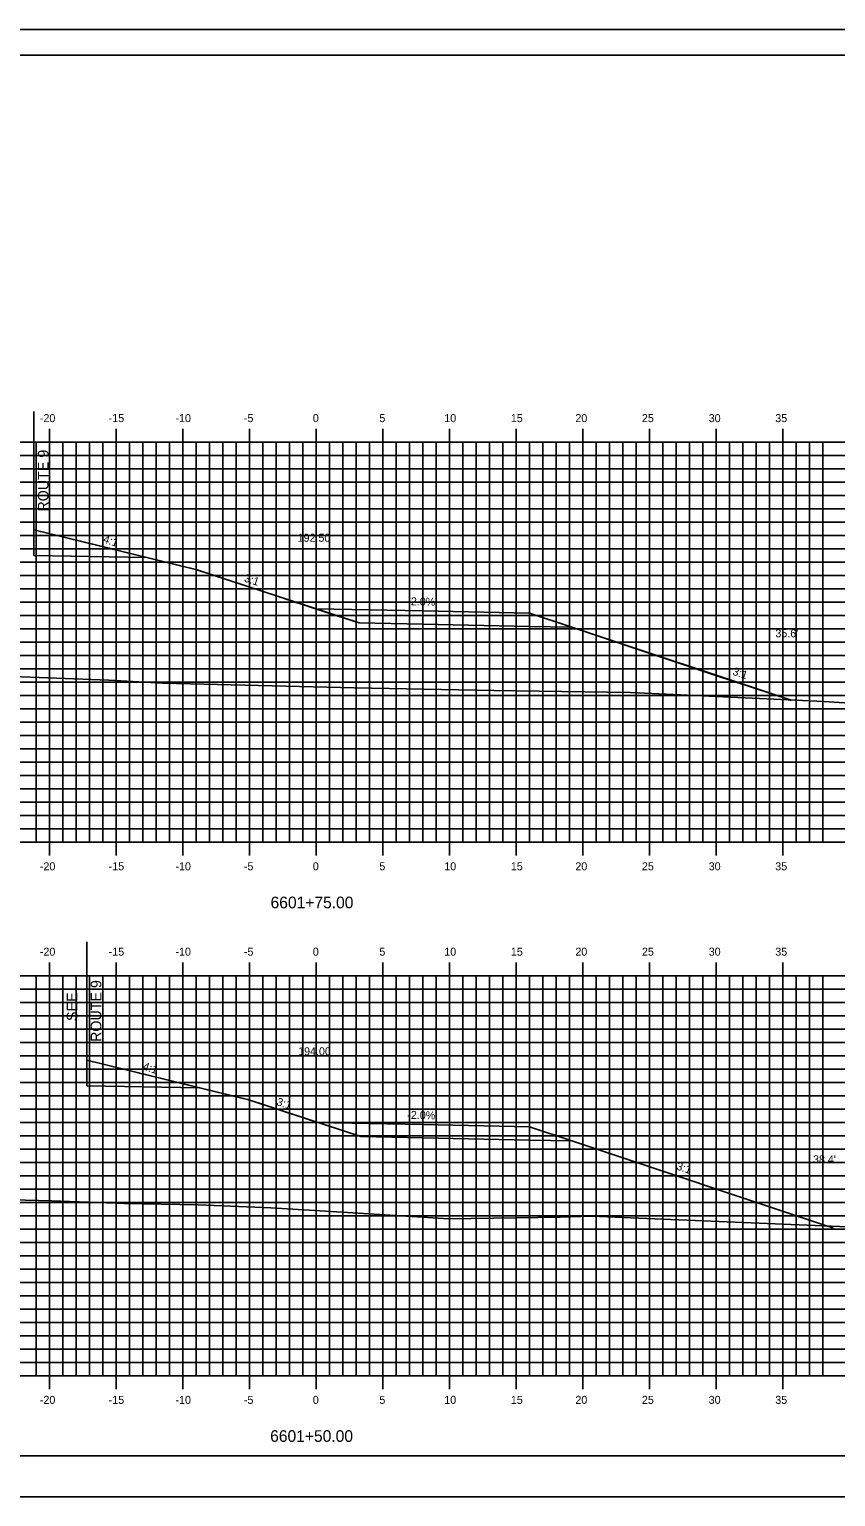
# Model space of a CAD drawing. Extents: x 1723740 to 1723911, y 459560 to 459670.
# Drawn here: x 1723801.2 to 1723861.7, y 459559.6 to 459669.6 of the extents above; entities that cross this region are included whole.
import ezdxf

# ---------------------------------------------------------------- set-up
doc = ezdxf.new("R2010")
doc.units = 0
for name, color, linetype in [('ANNOTATION', 7, 'Continuous'), ('BORDER', 7, 'Continuous'), ('D_Roadway_Centerline', 7, 'Continuous'), ('D_Roadway_Centerline_Text', 7, 'Continuous'), ('D_Roadway_Drive_Gravel', 7, 'Continuous'), ('D_Roadway_Edge_Shoulder', 7, 'Continuous'), ('D_Roadway_SlopeLines', 7, 'Continuous'), ('D_Roadway_SubGrade', 7, 'Continuous'), ('D_Text_Standard', 7, 'Continuous'), ('H_V ANNOTATION', 7, 'Continuous'), ('MAJOR', 7, 'Continuous'), ('MINOR', 7, 'Continuous'), ('PLOT BOUNDARY', 7, 'Continuous'), ('S_Roadway_Centerline', 7, 'Continuous')]:
    doc.layers.add(name, color=color, linetype=linetype)

msp = doc.modelspace()

# ---------------------------------------------------------------- linework, layer by layer
for points in [[(1723822.72, 459626.11), (1723830.72, 459625.95), (1723838.72, 459625.79), (1723841.91, 459624.73), (1723847.19, 459622.97), (1723849.96, 459622.05), (1723852.64, 459621.15), (1723858.27, 459619.28), (1723858.3, 459619.27), (1723858.35, 459619.25), (1723858.35, 459619.25)], [(1723822.72, 459587.61), (1723830.72, 459587.45), (1723838.72, 459587.29), (1723841.91, 459586.23), (1723861.07, 459579.84), (1723861.14, 459579.82), (1723861.15, 459579.81), (1723861.21, 459579.8), (1723861.25, 459579.78), (1723861.31, 459579.76), (1723861.33, 459579.75), (1723861.39, 459579.73), (1723861.42, 459579.73), (1723861.48, 459579.71), (1723861.51, 459579.7)]]:
    msp.add_lwpolyline(points)
at = {"layer": 'BORDER'}
msp.add_lwpolyline([(1723747.72, 459562.61), (1723907.72, 459562.61), (1723907.72, 459667.61), (1723747.72, 459667.61)], close=True, dxfattribs=at)
at = {"layer": 'D_Roadway_Centerline'}
for points in [[(1723801.56, 459632.04), (1723806.9, 459630.73), (1723807.2, 459630.66), (1723807.35, 459630.62), (1723810.03, 459629.96), (1723813.69, 459629.07), (1723813.71, 459629.06), (1723813.73, 459629.05), (1723813.73, 459629.05), (1723814.56, 459628.78), (1723814.77, 459628.71), (1723820.12, 459626.96), (1723820.64, 459626.79), (1723822.22, 459626.27), (1723823.76, 459625.77), (1723825.95, 459625.05)], [(1723805.53, 459592.28), (1723809.31, 459591.35), (1723809.66, 459591.26), (1723810.02, 459591.18), (1723813.99, 459590.2), (1723815.7, 459589.78), (1723817.68, 459589.3), (1723822.09, 459587.85), (1723822.7, 459587.65), (1723822.83, 459587.61)]]:
    msp.add_lwpolyline(points, dxfattribs=at)
at = {"layer": 'D_Roadway_Drive_Gravel'}
for points in [[(1723822.72, 459626.11), (1723822.72, 459626.11), (1723830.72, 459625.95), (1723838.72, 459625.79), (1723841.91, 459624.73), (1723838.72, 459624.79), (1723830.72, 459624.95), (1723825.95, 459625.05)], [(1723822.83, 459587.61), (1723830.72, 459587.45), (1723838.72, 459587.29), (1723841.91, 459586.23), (1723838.72, 459586.29), (1723830.72, 459586.45), (1723826.08, 459586.55)]]:
    msp.add_lwpolyline(points, dxfattribs=at)
at = {"layer": 'D_Roadway_Edge_Shoulder'}
for p, q in [((1723801.56, 459632.04), (1723801.56, 459631.79)), ((1723801.56, 459632.04), (1723801.56, 459631.79)), ((1723805.53, 459592.28), (1723805.53, 459592.03)), ((1723805.53, 459592.28), (1723805.53, 459592.03))]:
    msp.add_line(p, q, dxfattribs=at)
at = {"layer": 'D_Roadway_SlopeLines'}
for points in [[(1723801.56, 459632.04), (1723813.71, 459629.06), (1723825.95, 459625.05)], [(1723801.56, 459632.04), (1723813.71, 459629.06), (1723825.95, 459625.05)], [(1723801.56, 459632.04), (1723813.71, 459629.06), (1723825.95, 459625.05)], [(1723801.56, 459632.04), (1723813.71, 459629.06), (1723825.95, 459625.05)], [(1723801.56, 459632.04), (1723813.71, 459629.06), (1723825.95, 459625.05)], [(1723801.56, 459632.04), (1723813.71, 459629.06), (1723825.95, 459625.05)], [(1723801.56, 459632.04), (1723813.71, 459629.06), (1723825.95, 459625.05)], [(1723838.72, 459625.79), (1723841.91, 459624.73), (1723858.27, 459619.28)], [(1723805.53, 459592.28), (1723817.68, 459589.3), (1723826.08, 459586.55)], [(1723805.53, 459592.28), (1723817.68, 459589.3), (1723826.08, 459586.55)], [(1723805.53, 459592.28), (1723817.68, 459589.3), (1723826.08, 459586.55)], [(1723805.53, 459592.28), (1723817.68, 459589.3), (1723826.08, 459586.55)], [(1723805.53, 459592.28), (1723817.68, 459589.3), (1723826.08, 459586.55)], [(1723805.53, 459592.28), (1723817.68, 459589.3), (1723826.08, 459586.55)], [(1723805.53, 459592.28), (1723817.68, 459589.3), (1723826.08, 459586.55)], [(1723838.72, 459587.29), (1723841.91, 459586.23), (1723861.07, 459579.84)]]:
    msp.add_lwpolyline(points, dxfattribs=at)
at = {"layer": 'D_Roadway_SubGrade'}
for p, q in [((1723801.56, 459640.9), (1723801.56, 459630.12)), ((1723805.53, 459601.14), (1723805.53, 459590.35))]:
    msp.add_line(p, q, dxfattribs=at)
for points in [[(1723801.56, 459631.79), (1723801.56, 459632.04), (1723810.03, 459629.96), (1723801.56, 459630.12)], [(1723801.56, 459631.79), (1723801.56, 459632.04), (1723810.03, 459629.96), (1723801.56, 459630.12)], [(1723805.53, 459592.03), (1723805.53, 459592.28), (1723813.99, 459590.2), (1723805.53, 459590.35)], [(1723805.53, 459592.03), (1723805.53, 459592.28), (1723813.99, 459590.2), (1723805.53, 459590.35)], [(1723805.53, 459592.03), (1723805.53, 459592.28), (1723813.99, 459590.2), (1723805.53, 459590.35)], [(1723805.53, 459592.03), (1723805.53, 459592.28), (1723813.99, 459590.2), (1723805.53, 459590.35)]]:
    msp.add_lwpolyline(points, dxfattribs=at)
at = {"layer": 'MAJOR'}
for p, q in [((1723802.72, 459639.61), (1723802.72, 459638.61)), ((1723807.72, 459639.61), (1723807.72, 459638.61)), ((1723812.72, 459639.61), (1723812.72, 459638.61)), ((1723817.72, 459639.61), (1723817.72, 459638.61)), ((1723822.72, 459639.61), (1723822.72, 459638.61)), ((1723827.72, 459639.61), (1723827.72, 459638.61)), ((1723832.72, 459639.61), (1723832.72, 459638.61)), ((1723837.72, 459639.61), (1723837.72, 459638.61)), ((1723842.72, 459639.61), (1723842.72, 459638.61)), ((1723847.72, 459639.61), (1723847.72, 459638.61)), ((1723852.72, 459639.61), (1723852.72, 459638.61)), ((1723857.72, 459639.61), (1723857.72, 459638.61)), ((1723752.72, 459638.61), (1723892.72, 459638.61)), ((1723752.72, 459638.61), (1723892.72, 459638.61)), ((1723802.72, 459608.61), (1723802.72, 459638.61)), ((1723807.72, 459608.61), (1723807.72, 459638.61)), ((1723812.72, 459608.61), (1723812.72, 459638.61)), ((1723817.72, 459608.61), (1723817.72, 459638.61)), ((1723822.72, 459608.61), (1723822.72, 459638.61)), ((1723827.72, 459608.61), (1723827.72, 459638.61)), ((1723832.72, 459608.61), (1723832.72, 459638.61)), ((1723837.72, 459608.61), (1723837.72, 459638.61)), ((1723842.72, 459608.61), (1723842.72, 459638.61)), ((1723847.72, 459608.61), (1723847.72, 459638.61)), ((1723852.72, 459608.61), (1723852.72, 459638.61)), ((1723857.72, 459608.61), (1723857.72, 459638.61)), ((1723752.72, 459633.61), (1723892.72, 459633.61)), ((1723752.72, 459628.61), (1723892.72, 459628.61)), ((1723752.72, 459623.61), (1723892.72, 459623.61)), ((1723752.72, 459618.61), (1723892.72, 459618.61)), ((1723752.72, 459613.61), (1723892.72, 459613.61)), ((1723752.72, 459608.61), (1723892.72, 459608.61)), ((1723752.72, 459608.61), (1723892.72, 459608.61)), ((1723802.72, 459607.61), (1723802.72, 459608.61)), ((1723807.72, 459607.61), (1723807.72, 459608.61)), ((1723812.72, 459607.61), (1723812.72, 459608.61)), ((1723817.72, 459607.61), (1723817.72, 459608.61)), ((1723822.72, 459607.61), (1723822.72, 459608.61)), ((1723827.72, 459607.61), (1723827.72, 459608.61)), ((1723832.72, 459607.61), (1723832.72, 459608.61)), ((1723837.72, 459607.61), (1723837.72, 459608.61)), ((1723842.72, 459607.61), (1723842.72, 459608.61)), ((1723847.72, 459607.61), (1723847.72, 459608.61)), ((1723852.72, 459607.61), (1723852.72, 459608.61)), ((1723857.72, 459607.61), (1723857.72, 459608.61)), ((1723802.72, 459599.61), (1723802.72, 459598.61)), ((1723807.72, 459599.61), (1723807.72, 459598.61)), ((1723812.72, 459599.61), (1723812.72, 459598.61)), ((1723817.72, 459599.61), (1723817.72, 459598.61)), ((1723822.72, 459599.61), (1723822.72, 459598.61)), ((1723827.72, 459599.61), (1723827.72, 459598.61)), ((1723832.72, 459599.61), (1723832.72, 459598.61)), ((1723837.72, 459599.61), (1723837.72, 459598.61)), ((1723842.72, 459599.61), (1723842.72, 459598.61)), ((1723847.72, 459599.61), (1723847.72, 459598.61)), ((1723852.72, 459599.61), (1723852.72, 459598.61)), ((1723857.72, 459599.61), (1723857.72, 459598.61)), ((1723752.72, 459598.61), (1723892.72, 459598.61)), ((1723752.72, 459598.61), (1723892.72, 459598.61)), ((1723802.72, 459568.61), (1723802.72, 459598.61)), ((1723807.72, 459568.61), (1723807.72, 459598.61)), ((1723812.72, 459568.61), (1723812.72, 459598.61)), ((1723817.72, 459568.61), (1723817.72, 459598.61)), ((1723822.72, 459568.61), (1723822.72, 459598.61)), ((1723827.72, 459568.61), (1723827.72, 459598.61)), ((1723832.72, 459568.61), (1723832.72, 459598.61)), ((1723837.72, 459568.61), (1723837.72, 459598.61)), ((1723842.72, 459568.61), (1723842.72, 459598.61)), ((1723847.72, 459568.61), (1723847.72, 459598.61)), ((1723852.72, 459568.61), (1723852.72, 459598.61)), ((1723857.72, 459568.61), (1723857.72, 459598.61)), ((1723752.72, 459593.61), (1723892.72, 459593.61)), ((1723752.72, 459588.61), (1723892.72, 459588.61)), ((1723752.72, 459583.61), (1723892.72, 459583.61)), ((1723752.72, 459578.61), (1723892.72, 459578.61)), ((1723752.72, 459573.61), (1723892.72, 459573.61)), ((1723752.72, 459568.61), (1723892.72, 459568.61)), ((1723752.72, 459568.61), (1723892.72, 459568.61)), ((1723802.72, 459567.61), (1723802.72, 459568.61)), ((1723807.72, 459567.61), (1723807.72, 459568.61)), ((1723812.72, 459567.61), (1723812.72, 459568.61)), ((1723817.72, 459567.61), (1723817.72, 459568.61)), ((1723822.72, 459567.61), (1723822.72, 459568.61)), ((1723827.72, 459567.61), (1723827.72, 459568.61)), ((1723832.72, 459567.61), (1723832.72, 459568.61)), ((1723837.72, 459567.61), (1723837.72, 459568.61)), ((1723842.72, 459567.61), (1723842.72, 459568.61)), ((1723847.72, 459567.61), (1723847.72, 459568.61)), ((1723852.72, 459567.61), (1723852.72, 459568.61)), ((1723857.72, 459567.61), (1723857.72, 459568.61))]:
    msp.add_line(p, q, dxfattribs=at)
at = {"layer": 'MINOR'}
for p, q in [((1723801.72, 459608.61), (1723801.72, 459638.61)), ((1723803.72, 459608.61), (1723803.72, 459638.61)), ((1723804.72, 459608.61), (1723804.72, 459638.61)), ((1723805.72, 459608.61), (1723805.72, 459638.61)), ((1723806.72, 459608.61), (1723806.72, 459638.61)), ((1723808.72, 459608.61), (1723808.72, 459638.61)), ((1723809.72, 459608.61), (1723809.72, 459638.61)), ((1723810.72, 459608.61), (1723810.72, 459638.61)), ((1723811.72, 459608.61), (1723811.72, 459638.61)), ((1723813.72, 459608.61), (1723813.72, 459638.61)), ((1723814.72, 459608.61), (1723814.72, 459638.61)), ((1723815.72, 459608.61), (1723815.72, 459638.61)), ((1723816.72, 459608.61), (1723816.72, 459638.61)), ((1723818.72, 459608.61), (1723818.72, 459638.61)), ((1723819.72, 459608.61), (1723819.72, 459638.61)), ((1723820.72, 459608.61), (1723820.72, 459638.61)), ((1723821.72, 459608.61), (1723821.72, 459638.61)), ((1723823.72, 459608.61), (1723823.72, 459638.61)), ((1723824.72, 459608.61), (1723824.72, 459638.61)), ((1723825.72, 459608.61), (1723825.72, 459638.61)), ((1723826.72, 459608.61), (1723826.72, 459638.61)), ((1723828.72, 459608.61), (1723828.72, 459638.61)), ((1723829.72, 459608.61), (1723829.72, 459638.61)), ((1723830.72, 459608.61), (1723830.72, 459638.61)), ((1723831.72, 459608.61), (1723831.72, 459638.61)), ((1723833.72, 459608.61), (1723833.72, 459638.61)), ((1723834.72, 459608.61), (1723834.72, 459638.61)), ((1723835.72, 459608.61), (1723835.72, 459638.61)), ((1723836.72, 459608.61), (1723836.72, 459638.61)), ((1723838.72, 459608.61), (1723838.72, 459638.61)), ((1723839.72, 459608.61), (1723839.72, 459638.61)), ((1723840.72, 459608.61), (1723840.72, 459638.61)), ((1723841.72, 459608.61), (1723841.72, 459638.61)), ((1723843.72, 459608.61), (1723843.72, 459638.61)), ((1723844.72, 459608.61), (1723844.72, 459638.61)), ((1723845.72, 459608.61), (1723845.72, 459638.61)), ((1723846.72, 459608.61), (1723846.72, 459638.61)), ((1723848.72, 459608.61), (1723848.72, 459638.61)), ((1723849.72, 459608.61), (1723849.72, 459638.61)), ((1723850.72, 459608.61), (1723850.72, 459638.61)), ((1723851.72, 459608.61), (1723851.72, 459638.61)), ((1723853.72, 459608.61), (1723853.72, 459638.61)), ((1723854.72, 459608.61), (1723854.72, 459638.61)), ((1723855.72, 459608.61), (1723855.72, 459638.61)), ((1723856.72, 459608.61), (1723856.72, 459638.61)), ((1723858.72, 459608.61), (1723858.72, 459638.61)), ((1723859.72, 459608.61), (1723859.72, 459638.61)), ((1723860.72, 459608.61), (1723860.72, 459638.61)), ((1723752.72, 459637.61), (1723892.72, 459637.61)), ((1723752.72, 459636.61), (1723892.72, 459636.61)), ((1723752.72, 459635.61), (1723892.72, 459635.61)), ((1723752.72, 459634.61), (1723892.72, 459634.61)), ((1723752.72, 459632.61), (1723892.72, 459632.61)), ((1723752.72, 459631.61), (1723892.72, 459631.61)), ((1723752.72, 459630.61), (1723892.72, 459630.61)), ((1723752.72, 459629.61), (1723892.72, 459629.61)), ((1723752.72, 459627.61), (1723892.72, 459627.61)), ((1723752.72, 459626.61), (1723892.72, 459626.61)), ((1723752.72, 459625.61), (1723892.72, 459625.61)), ((1723752.72, 459624.61), (1723892.72, 459624.61)), ((1723752.72, 459622.61), (1723892.72, 459622.61)), ((1723752.72, 459621.61), (1723892.72, 459621.61)), ((1723752.72, 459620.61), (1723892.72, 459620.61)), ((1723752.72, 459619.61), (1723892.72, 459619.61)), ((1723752.72, 459617.61), (1723892.72, 459617.61)), ((1723752.72, 459616.61), (1723892.72, 459616.61)), ((1723752.72, 459615.61), (1723892.72, 459615.61)), ((1723752.72, 459614.61), (1723892.72, 459614.61)), ((1723752.72, 459612.61), (1723892.72, 459612.61)), ((1723752.72, 459611.61), (1723892.72, 459611.61)), ((1723752.72, 459610.61), (1723892.72, 459610.61)), ((1723752.72, 459609.61), (1723892.72, 459609.61)), ((1723752.72, 459597.61), (1723892.72, 459597.61)), ((1723801.72, 459568.61), (1723801.72, 459598.61)), ((1723803.72, 459568.61), (1723803.72, 459598.61)), ((1723804.72, 459568.61), (1723804.72, 459598.61)), ((1723805.72, 459568.61), (1723805.72, 459598.61)), ((1723806.72, 459568.61), (1723806.72, 459598.61)), ((1723808.72, 459568.61), (1723808.72, 459598.61)), ((1723809.72, 459568.61), (1723809.72, 459598.61)), ((1723810.72, 459568.61), (1723810.72, 459598.61)), ((1723811.72, 459568.61), (1723811.72, 459598.61)), ((1723813.72, 459568.61), (1723813.72, 459598.61)), ((1723814.72, 459568.61), (1723814.72, 459598.61)), ((1723815.72, 459568.61), (1723815.72, 459598.61)), ((1723816.72, 459568.61), (1723816.72, 459598.61)), ((1723818.72, 459568.61), (1723818.72, 459598.61)), ((1723819.72, 459568.61), (1723819.72, 459598.61)), ((1723820.72, 459568.61), (1723820.72, 459598.61)), ((1723821.72, 459568.61), (1723821.72, 459598.61)), ((1723823.72, 459568.61), (1723823.72, 459598.61)), ((1723824.72, 459568.61), (1723824.72, 459598.61)), ((1723825.72, 459568.61), (1723825.72, 459598.61)), ((1723826.72, 459568.61), (1723826.72, 459598.61)), ((1723828.72, 459568.61), (1723828.72, 459598.61)), ((1723829.72, 459568.61), (1723829.72, 459598.61)), ((1723830.72, 459568.61), (1723830.72, 459598.61)), ((1723831.72, 459568.61), (1723831.72, 459598.61)), ((1723833.72, 459568.61), (1723833.72, 459598.61)), ((1723834.72, 459568.61), (1723834.72, 459598.61)), ((1723835.72, 459568.61), (1723835.72, 459598.61)), ((1723836.72, 459568.61), (1723836.72, 459598.61)), ((1723838.72, 459568.61), (1723838.72, 459598.61)), ((1723839.72, 459568.61), (1723839.72, 459598.61)), ((1723840.72, 459568.61), (1723840.72, 459598.61)), ((1723841.72, 459568.61), (1723841.72, 459598.61)), ((1723843.72, 459568.61), (1723843.72, 459598.61)), ((1723844.72, 459568.61), (1723844.72, 459598.61)), ((1723845.72, 459568.61), (1723845.72, 459598.61)), ((1723846.72, 459568.61), (1723846.72, 459598.61)), ((1723848.72, 459568.61), (1723848.72, 459598.61)), ((1723849.72, 459568.61), (1723849.72, 459598.61)), ((1723850.72, 459568.61), (1723850.72, 459598.61)), ((1723851.72, 459568.61), (1723851.72, 459598.61)), ((1723853.72, 459568.61), (1723853.72, 459598.61)), ((1723854.72, 459568.61), (1723854.72, 459598.61)), ((1723855.72, 459568.61), (1723855.72, 459598.61)), ((1723856.72, 459568.61), (1723856.72, 459598.61)), ((1723858.72, 459568.61), (1723858.72, 459598.61)), ((1723859.72, 459568.61), (1723859.72, 459598.61)), ((1723860.72, 459568.61), (1723860.72, 459598.61)), ((1723752.72, 459596.61), (1723892.72, 459596.61)), ((1723752.72, 459595.61), (1723892.72, 459595.61)), ((1723752.72, 459594.61), (1723892.72, 459594.61)), ((1723752.72, 459592.61), (1723892.72, 459592.61)), ((1723752.72, 459591.61), (1723892.72, 459591.61)), ((1723752.72, 459590.61), (1723892.72, 459590.61)), ((1723752.72, 459589.61), (1723892.72, 459589.61)), ((1723752.72, 459587.61), (1723892.72, 459587.61)), ((1723752.72, 459586.61), (1723892.72, 459586.61)), ((1723752.72, 459585.61), (1723892.72, 459585.61)), ((1723752.72, 459584.61), (1723892.72, 459584.61)), ((1723752.72, 459582.61), (1723892.72, 459582.61)), ((1723752.72, 459581.61), (1723892.72, 459581.61)), ((1723752.72, 459580.61), (1723892.72, 459580.61)), ((1723752.72, 459579.61), (1723892.72, 459579.61)), ((1723752.72, 459577.61), (1723892.72, 459577.61)), ((1723752.72, 459576.61), (1723892.72, 459576.61)), ((1723752.72, 459575.61), (1723892.72, 459575.61)), ((1723752.72, 459574.61), (1723892.72, 459574.61)), ((1723752.72, 459572.61), (1723892.72, 459572.61)), ((1723752.72, 459571.61), (1723892.72, 459571.61)), ((1723752.72, 459570.61), (1723892.72, 459570.61)), ((1723752.72, 459569.61), (1723892.72, 459569.61))]:
    msp.add_line(p, q, dxfattribs=at)
at = {"layer": 'PLOT BOUNDARY'}
msp.add_lwpolyline([(1723739.62, 459559.55), (1723909.62, 459559.55), (1723909.62, 459669.55), (1723739.62, 459669.55)], close=True, dxfattribs=at)
at = {"layer": 'S_Roadway_Centerline'}
for points in [[(1723752.72, 459622.54), (1723759.22, 459622.29), (1723760.58, 459622.19), (1723762.62, 459622.14), (1723773.54, 459621.89), (1723782.14, 459621.6), (1723787.53, 459621.52), (1723807.19, 459620.76), (1723811.22, 459620.55), (1723825.57, 459620.18), (1723836.05, 459620), (1723846.28, 459619.83), (1723860.82, 459619.16), (1723865.74, 459618.85), (1723869.67, 459618.76), (1723877.33, 459618.67), (1723886.57, 459618.54), (1723889.34, 459618.52), (1723891.65, 459618.48), (1723892.72, 459618.47)], [(1723752.72, 459582.84), (1723758.56, 459582.38), (1723762.18, 459582.27), (1723766.71, 459582.17), (1723774.4, 459582.14), (1723791, 459582.02), (1723802.91, 459581.73), (1723808.36, 459581.53), (1723813.88, 459581.43), (1723819.34, 459581.21), (1723825.09, 459580.85), (1723832.69, 459580.38), (1723841.04, 459580.51), (1723843.4, 459580.59), (1723845.73, 459580.48), (1723866.78, 459579.6), (1723868.76, 459579.54), (1723878.05, 459578.92), (1723890.34, 459578.54), (1723890.75, 459578.53), (1723892.72, 459578.43)]]:
    msp.add_lwpolyline(points, dxfattribs=at)

# ---------------------------------------------------------------- texts
at = {"layer": 'ANNOTATION'}
for s, height, rotation, p in [('ROUTE 9', 0.8, 90, (1723802.66, 459633.4)), ('4:1', 0.6, 341.5651, (1723806.71, 459631.1)), ('3:1', 0.6, 341.5651, (1723817.28, 459628.18)), ('-2.0%', 0.6, 358.8542, (1723829.56, 459626.38)), ('3:1', 0.6, 341.5651, (1723853.91, 459621.18)), ('ROUTE 9', 0.8, 90, (1723806.62, 459593.64)), ('SEE', 0.8, 90, (1723804.82, 459595.21)), ('4:1', 0.6, 341.5651, (1723809.68, 459591.58)), ('3:1', 0.6, 341.5651, (1723819.71, 459588.92)), ('-2.0%', 0.6, 358.8542, (1723829.56, 459587.88)), ('3:1', 0.6, 341.5651, (1723849.7, 459584.09))]:
    msp.add_text(s, height=height, rotation=rotation, dxfattribs=at).set_placement(p)
at = {"layer": 'D_Roadway_Centerline_Text'}
for s, p in [('192.50', (1723821.34, 459631.14)), ('194.00', (1723821.38, 459592.64))]:
    msp.add_text(s, height=0.6, dxfattribs=at).set_placement(p)
at = {"layer": 'D_Text_Standard'}
for s, p in [("35.6'", (1723857.17, 459623.98)), ("38.4'", (1723859.99, 459584.54))]:
    msp.add_text(s, height=0.6, dxfattribs=at).set_placement(p)
at = {"layer": 'H_V ANNOTATION'}
for s, height, p in [('-20', 0.6, (1723802.01, 459640.11)), ('-15', 0.6, (1723807.17, 459640.11)), ('-10', 0.6, (1723812.18, 459640.11)), ('-5', 0.6, (1723817.31, 459640.11)), ('0', 0.6, (1723822.48, 459640.11)), ('5', 0.6, (1723827.47, 459640.11)), ('10', 0.6, (1723832.34, 459640.11)), ('15', 0.6, (1723837.33, 459640.11)), ('20', 0.6, (1723842.17, 459640.11)), ('25', 0.6, (1723847.16, 459640.11)), ('30', 0.6, (1723852.17, 459640.11)), ('35', 0.6, (1723857.16, 459640.11)), ('-20', 0.6, (1723802.01, 459606.51)), ('-15', 0.6, (1723807.17, 459606.51)), ('-10', 0.6, (1723812.18, 459606.51)), ('-5', 0.6, (1723817.31, 459606.51)), ('0', 0.6, (1723822.48, 459606.51)), ('5', 0.6, (1723827.47, 459606.51)), ('10', 0.6, (1723832.34, 459606.51)), ('15', 0.6, (1723837.33, 459606.51)), ('20', 0.6, (1723842.17, 459606.51)), ('25', 0.6, (1723847.16, 459606.51)), ('30', 0.6, (1723852.17, 459606.51)), ('35', 0.6, (1723857.16, 459606.51)), ('6601+75.00', 0.875, (1723819.31, 459603.66)), ('-20', 0.6, (1723802.01, 459600.11)), ('-15', 0.6, (1723807.17, 459600.11)), ('-10', 0.6, (1723812.18, 459600.11)), ('-5', 0.6, (1723817.31, 459600.11)), ('0', 0.6, (1723822.48, 459600.11)), ('5', 0.6, (1723827.47, 459600.11)), ('10', 0.6, (1723832.34, 459600.11)), ('15', 0.6, (1723837.33, 459600.11)), ('20', 0.6, (1723842.17, 459600.11)), ('25', 0.6, (1723847.16, 459600.11)), ('30', 0.6, (1723852.17, 459600.11)), ('35', 0.6, (1723857.16, 459600.11)), ('-20', 0.6, (1723802.01, 459566.51)), ('-15', 0.6, (1723807.17, 459566.51)), ('-10', 0.6, (1723812.18, 459566.51)), ('-5', 0.6, (1723817.31, 459566.51)), ('0', 0.6, (1723822.48, 459566.51)), ('5', 0.6, (1723827.47, 459566.51)), ('10', 0.6, (1723832.34, 459566.51)), ('15', 0.6, (1723837.33, 459566.51)), ('20', 0.6, (1723842.17, 459566.51)), ('25', 0.6, (1723847.16, 459566.51)), ('30', 0.6, (1723852.17, 459566.51)), ('35', 0.6, (1723857.16, 459566.51)), ('6601+50.00', 0.875, (1723819.28, 459563.66))]:
    msp.add_text(s, height=height, dxfattribs=at).set_placement(p)

doc.saveas('drawing.dxf')
